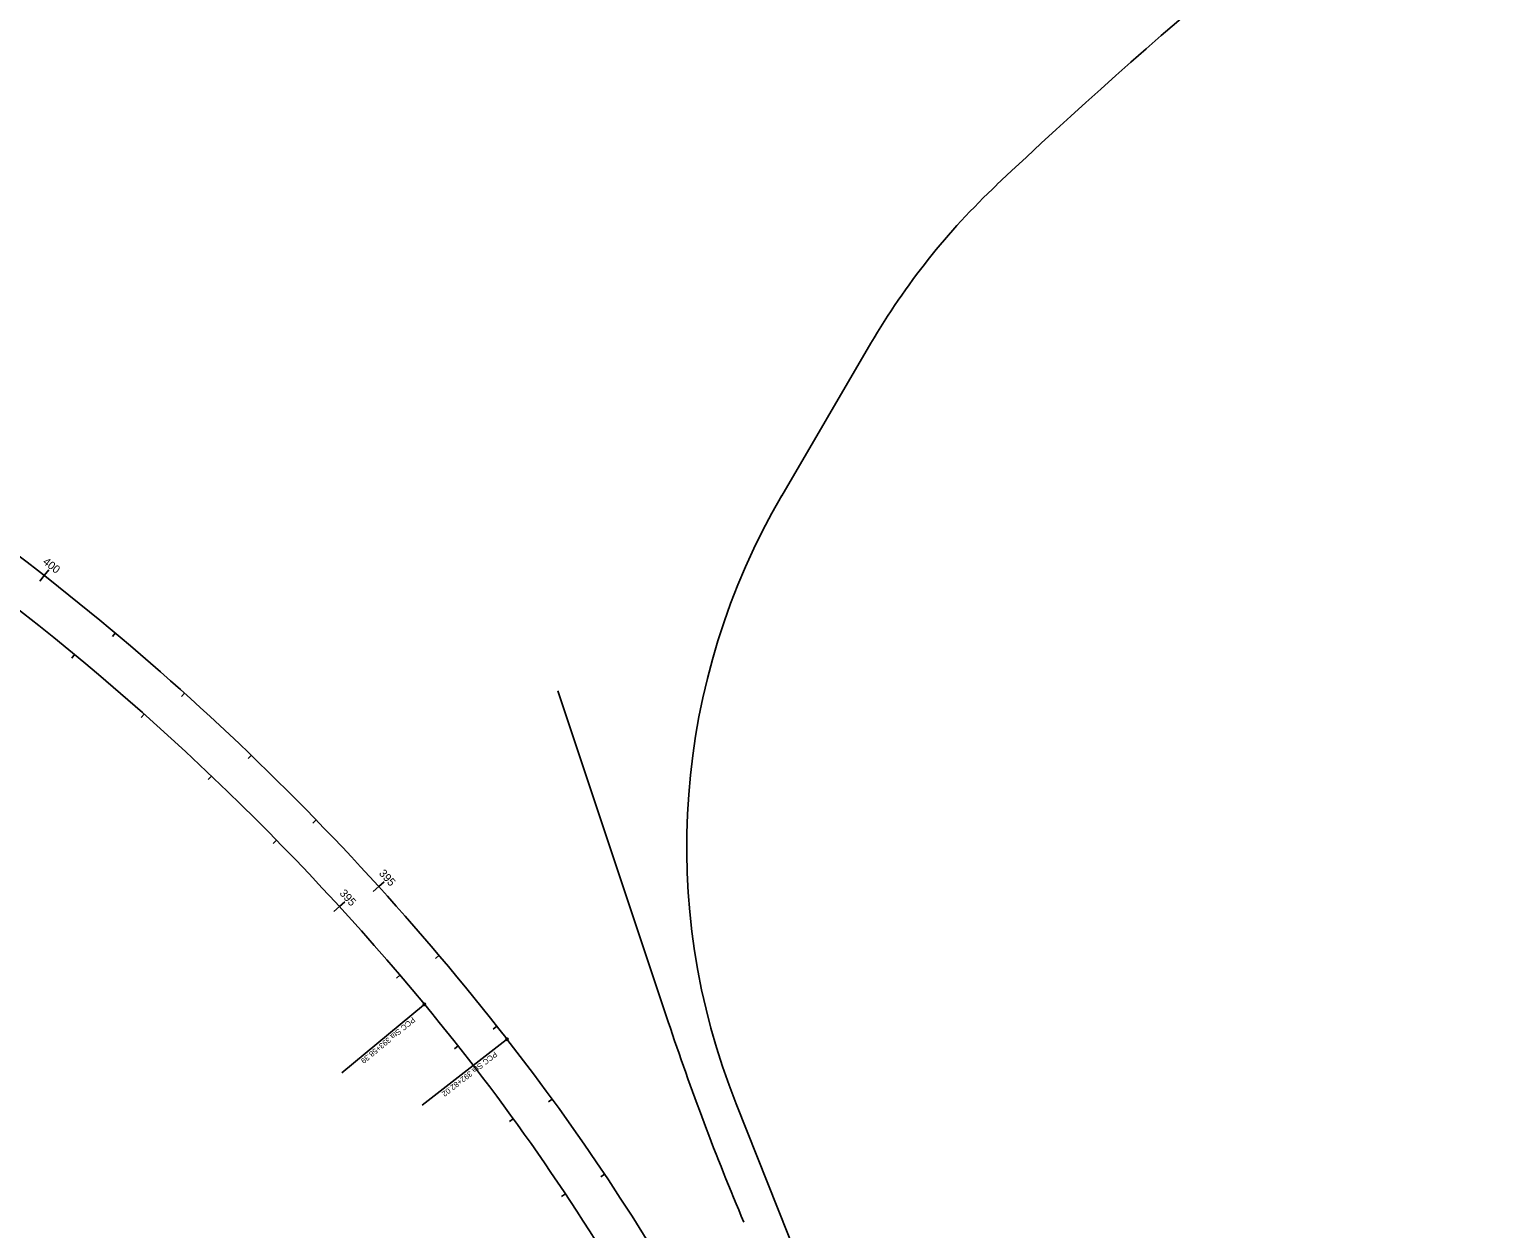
# Model space of a CAD drawing. Extents: x 1602163 to 1612907, y 1087635 to 1096265.
# Drawn here: x 1610701 to 1612299, y 1093265 to 1094576 of the extents above; entities that cross this region are included whole.
import ezdxf

# ---------------------------------------------------------------- set-up
doc = ezdxf.new("R2010")
doc.units = 0
for name, color, linetype in [('RD_HC_Cl', 7, 'Continuous'), ('RD_HC_CL_200', 7, 'Continuous'), ('RD_HC_Data_Tic', 7, 'Continuous'), ('RD_HC_Points', 7, 'Continuous'), ('RD_HC_TX_Sta50', 7, 'Continuous')]:
    doc.layers.add(name, color=color, linetype=linetype)

msp = doc.modelspace()

# ---------------------------------------------------------------- linework, layer by layer
at = {"layer": 'RD_HC_Cl'}
for centre, radius, start, end in [((1608910.9, 1091669.6), 2932.1, 37.9336, 56.1301), ((1608910.9, 1091669.6), 2885.6, 39.6334, 53.0731), ((1609225.7, 1091930.4), 2476.8, 20.7167, 39.6334), ((1609233.5, 1091921.1), 2523, 20.7167, 37.9336)]:
    msp.add_arc(centre, radius, start, end, dxfattribs=at)
at = {"layer": 'RD_HC_CL_200'}
for p, q in [((1611524, 1094066.3), (1611621.4, 1094233)), ((1611399.8, 1093491), (1611279.1, 1093852.8)), ((1611582.6, 1093128.9), (1611474, 1093401.3))]:
    msp.add_line(p, q, dxfattribs=at)
for centre, radius, start, end in [((1615878.6, 1090044), 6000, 126.62559, 133.35895), ((1612294.7, 1093839.2), 780, 133.359, 149.6819), ((1612180, 1093682.7), 760, 149.6819, 201.7343), ((1614245.6, 1094440.3), 3000, 198.4471, 202.9196)]:
    msp.add_arc(centre, radius, start, end, dxfattribs=at)
at = {"layer": 'RD_HC_Data_Tic'}
for p, q in [((1610717.5, 1093979), (1610712.6, 1093972.7)), ((1610717.5, 1093979), (1610722.4, 1093985.3)), ((1610795.2, 1093916), (1610792, 1093912.2)), ((1610750.7, 1093892.6), (1610747.5, 1093888.7)), ((1610870.7, 1093850.5), (1610867.4, 1093846.7)), ((1610826.6, 1093827.5), (1610823.3, 1093823.8)), ((1610943.9, 1093782.4), (1610940.5, 1093778.8)), ((1610900.2, 1093759.8), (1610896.8, 1093756.2)), ((1611014.8, 1093711.8), (1611011.2, 1093708.3)), ((1610971.5, 1093689.7), (1610967.9, 1093686.2)), ((1611083.2, 1093638.9), (1611089.1, 1093644.3)), ((1611083.2, 1093638.9), (1611077.3, 1093633.5)), ((1611040.2, 1093617), (1611034.3, 1093611.6)), ((1611040.2, 1093617), (1611046.1, 1093622.4)), ((1611149.1, 1093563.7), (1611145.3, 1093560.4)), ((1611106.4, 1093542.1), (1611102.6, 1093538.9)), ((1611212.4, 1093486.2), (1611208.5, 1093483.1)), ((1611169.9, 1093464.8), (1611166, 1093461.7)), ((1611272.8, 1093406.6), (1611268.8, 1093403.7)), ((1611230.3, 1093385.1), (1611226.2, 1093382.2)), ((1611330.1, 1093324.6), (1611326, 1093321.8)), ((1611287.3, 1093303), (1611283.2, 1093300.2))]:
    msp.add_line(p, q, dxfattribs=at)
at = {"layer": 'RD_HC_Points'}
for p, q in [((1611132.2, 1093509.4), (1611042.9, 1093435.4)), ((1611222.5, 1093471.3), (1611130.8, 1093399.9))]:
    msp.add_line(p, q, dxfattribs=at)
for centre in [(1611133.2, 1093510.2), (1611223.5, 1093472.1)]:
    msp.add_circle(centre, 1.25, dxfattribs=at)

# ---------------------------------------------------------------- texts
for s, rotation, p in [('PCC Sta 393+58.39', 219.6334, (1611120, 1093496.7)), ('PCC Sta 392+82.02', 217.9336, (1611209.9, 1093459))]:
    msp.add_text(s, height=6, rotation=rotation, dxfattribs=at).set_placement(p)
at = {"layer": 'RD_HC_TX_Sta50'}
for s, rotation, p in [('400', 321.9637, (1610715.2, 1093992.6)), ('395', 312.1931, (1611082.9, 1093653)), ('395', 312.4452, (1611039.8, 1093631.2))]:
    msp.add_text(s, height=8.75, rotation=rotation, dxfattribs=at).set_placement(p)

doc.saveas('drawing.dxf')
